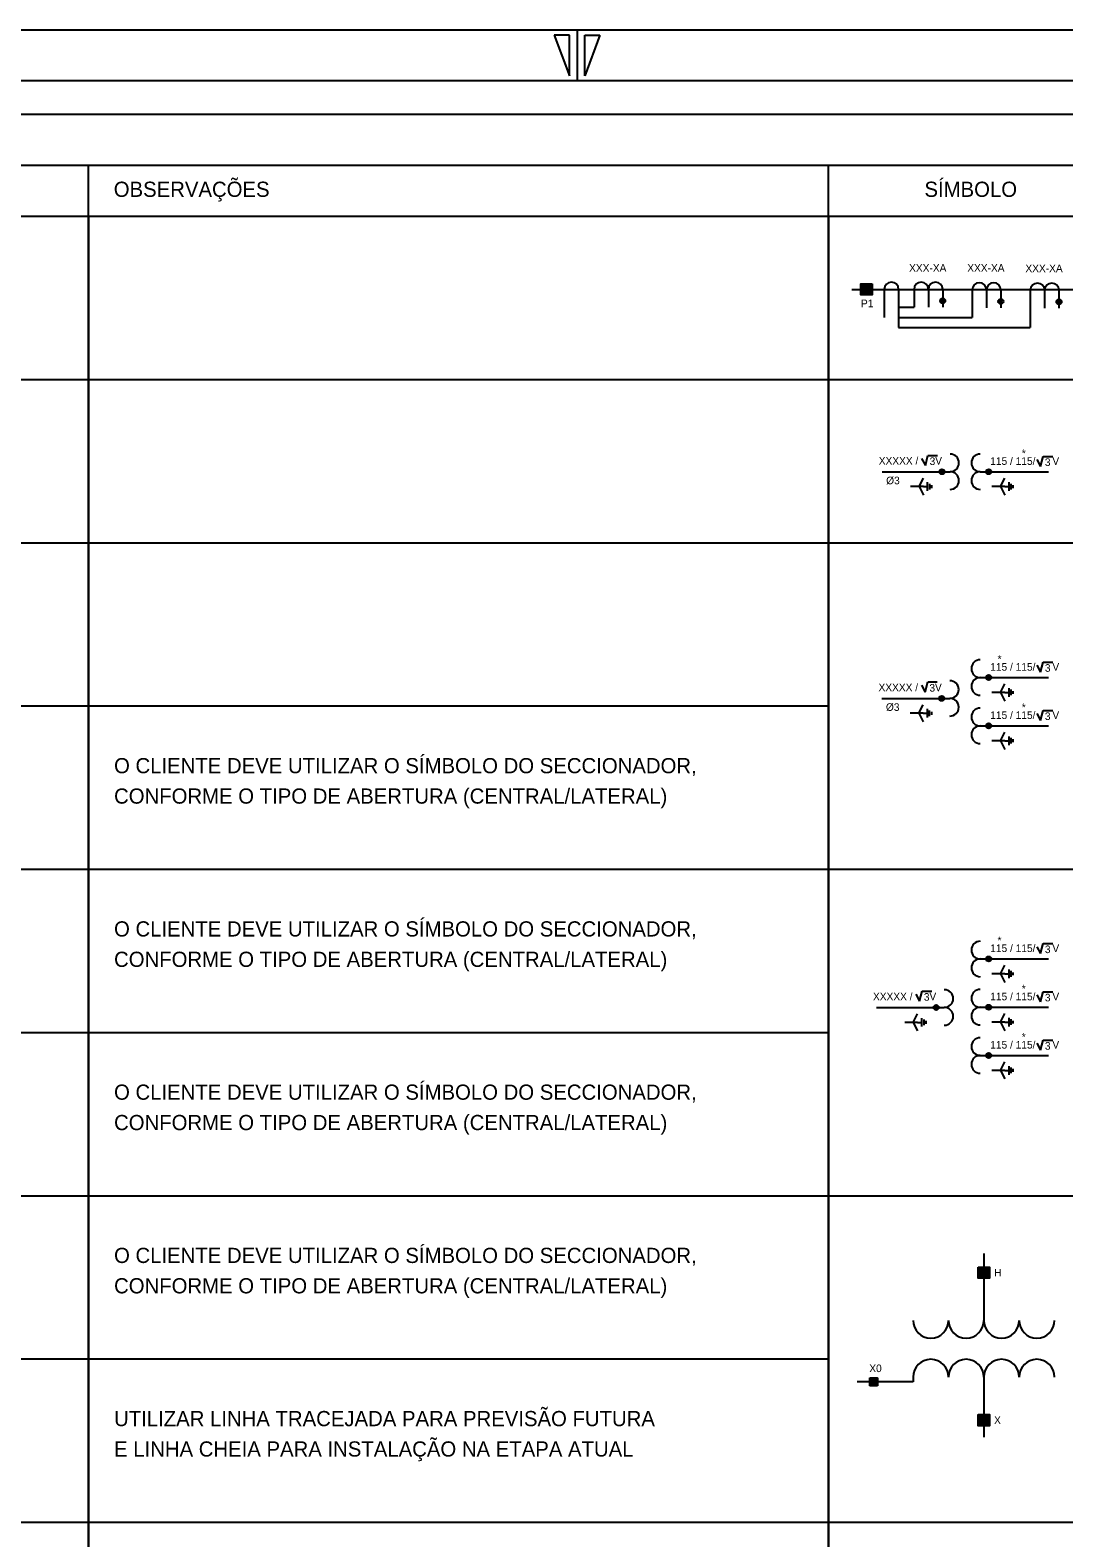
# Model space of a CAD drawing. Extents: x 563 to 3226, y 358 to 960.
# Drawn here: x 795.6 to 999.7, y 654.3 to 952 of the extents above; entities that cross this region are included whole.
import ezdxf

# ---------------------------------------------------------------- set-up
doc = ezdxf.new("R2010")
doc.units = 0
for name, color, linetype in [('COMENTÁRIOS_CEMIG_03-12-2019', 7, 'Continuous'), ('Default', 7, 'Continuous'), ('New Level (0)', 7, 'Continuous')]:
    doc.layers.add(name, color=color, linetype=linetype)

msp = doc.modelspace()

# ---------------------------------------------------------------- linework, layer by layer
at = {"layer": 'COMENTÁRIOS_CEMIG_03-12-2019'}
for p, q in [((959.63, 901.76), (961.72, 899.67)), ((959.63, 901.58), (961.54, 899.67)), ((959.63, 901.41), (961.37, 899.67)), ((959.63, 901.23), (961.19, 899.67)), ((959.63, 901.05), (961.01, 899.67)), ((959.63, 900.88), (960.84, 899.67)), ((959.63, 900.7), (960.66, 899.67)), ((959.63, 900.52), (960.48, 899.67)), ((959.63, 900.35), (960.31, 899.67)), ((959.63, 900.17), (960.13, 899.67)), ((959.63, 899.99), (959.95, 899.67)), ((959.63, 899.82), (959.78, 899.67)), ((959.69, 901.88), (961.84, 899.73)), ((959.86, 901.88), (961.84, 899.9)), ((960.04, 901.88), (961.84, 900.08)), ((960.22, 901.88), (961.84, 900.26)), ((960.39, 901.88), (961.84, 900.43)), ((960.57, 901.88), (961.84, 900.61)), ((960.75, 901.88), (961.84, 900.79)), ((960.92, 901.88), (961.84, 900.96)), ((961.1, 901.88), (961.84, 901.14)), ((961.28, 901.88), (961.84, 901.32)), ((961.45, 901.88), (961.84, 901.49)), ((961.63, 901.88), (961.84, 901.67)), ((961.81, 901.88), (961.84, 901.85)), ((982.78, 705.59), (984.93, 707.74)), ((982.78, 705.76), (984.75, 707.74)), ((982.78, 705.94), (984.57, 707.74)), ((982.78, 706.12), (984.4, 707.74)), ((982.78, 706.29), (984.22, 707.74)), ((982.78, 706.47), (984.04, 707.74)), ((982.78, 706.65), (983.87, 707.74)), ((982.78, 706.83), (983.69, 707.74)), ((982.78, 707), (983.51, 707.74)), ((982.78, 707.18), (983.34, 707.74)), ((982.78, 707.36), (983.16, 707.74)), ((982.78, 707.53), (982.98, 707.74)), ((982.78, 707.71), (982.81, 707.74)), ((982.89, 705.53), (984.99, 707.62)), ((983.07, 705.53), (984.99, 707.45)), ((983.25, 705.53), (984.99, 707.27)), ((983.42, 705.53), (984.99, 707.09)), ((983.6, 705.53), (984.99, 706.92)), ((983.78, 705.53), (984.99, 706.74)), ((983.95, 705.53), (984.99, 706.56)), ((984.13, 705.53), (984.99, 706.38)), ((984.31, 705.53), (984.99, 706.21)), ((984.49, 705.53), (984.99, 706.03)), ((984.66, 705.53), (984.99, 705.85)), ((984.84, 705.53), (984.99, 705.68)), ((982.78, 676.47), (984.93, 678.62)), ((982.78, 676.65), (984.75, 678.62)), ((982.78, 676.82), (984.57, 678.62)), ((982.78, 677), (984.4, 678.62)), ((982.78, 677.18), (984.22, 678.62)), ((982.78, 677.35), (984.04, 678.62)), ((982.78, 677.53), (983.87, 678.62)), ((982.78, 677.71), (983.69, 678.62)), ((982.78, 677.88), (983.51, 678.62)), ((982.78, 678.06), (983.34, 678.62)), ((982.78, 678.24), (983.16, 678.62)), ((982.78, 678.41), (982.98, 678.62)), ((982.78, 678.59), (982.81, 678.62)), ((982.89, 676.41), (984.99, 678.5)), ((983.07, 676.41), (984.99, 678.33)), ((983.25, 676.41), (984.99, 678.15)), ((983.42, 676.41), (984.99, 677.97)), ((983.6, 676.41), (984.99, 677.8)), ((983.78, 676.41), (984.99, 677.62)), ((983.95, 676.41), (984.99, 677.44)), ((984.13, 676.41), (984.99, 677.27)), ((984.31, 676.41), (984.99, 677.09)), ((984.49, 676.41), (984.99, 676.91)), ((984.66, 676.41), (984.99, 676.73)), ((984.84, 676.41), (984.99, 676.56))]:
    msp.add_line(p, q, dxfattribs=at)
for points in [[(961.84, 901.88), (961.84, 899.67), (959.63, 899.67), (959.63, 901.88)], [(982.78, 707.74), (984.99, 707.74), (984.99, 705.53), (982.78, 705.53)], [(982.78, 678.62), (984.99, 678.62), (984.99, 676.41), (982.78, 676.41)]]:
    msp.add_lwpolyline(points, close=True, dxfattribs=at)
at = {"layer": 'Default'}
for p, q in [((957.79, 900.78), (1006.04, 900.78)), ((964.22, 900.78), (964.22, 895.24)), ((964.22, 900.78), (964.22, 895.24)), ((967.05, 900.78), (967.05, 897.24)), ((967.05, 900.78), (967.05, 893.24)), ((970.1, 900.78), (970.1, 897.24)), ((970.1, 900.78), (970.1, 897.24)), ((972.93, 900.78), (972.93, 897.24)), ((972.93, 900.78), (972.93, 897.24)), ((975.76, 900.78), (975.76, 897.24)), ((975.76, 900.78), (975.76, 897.24)), ((981.58, 900.68), (981.58, 895.24)), ((984.41, 900.68), (984.41, 897.15)), ((987.24, 900.68), (987.24, 897.15)), ((993.06, 900.59), (993.06, 893.24)), ((995.89, 900.59), (995.89, 897.05)), ((998.72, 900.59), (998.72, 897.05)), ((967.05, 897.24), (970.1, 897.24)), ((967.05, 895.24), (981.58, 895.24)), ((967.05, 893.24), (993.06, 893.24)), ((971.6, 867.37), (972.35, 866)), ((972.35, 866), (972.85, 868)), ((972.85, 868), (974.74, 868)), ((994.35, 867.19), (995.1, 865.81)), ((995.1, 865.81), (995.6, 867.81)), ((995.6, 867.81), (997.49, 867.81)), ((963.81, 864.77), (977.22, 864.77)), ((971.09, 861.83), (971.94, 863.53)), ((983.17, 864.77), (996.68, 864.77)), ((987.15, 861.83), (988, 863.53)), ((971.09, 861.83), (969.4, 861.83)), ((971.94, 861.83), (971.09, 861.83)), ((971.09, 861.83), (971.94, 860.13)), ((971.94, 861.83), (972.79, 861.83)), ((972.79, 861.83), (972.79, 862.68)), ((972.79, 860.98), (972.79, 861.83)), ((973.22, 861.83), (973.22, 862.39)), ((973.22, 861.26), (973.22, 861.83)), ((973.64, 861.83), (973.64, 862.11)), ((973.64, 861.54), (973.64, 861.83)), ((987.15, 861.83), (985.46, 861.83)), ((988, 861.83), (987.15, 861.83)), ((987.15, 861.83), (988, 860.13)), ((988, 861.83), (988.85, 861.83)), ((988.85, 861.83), (988.85, 862.68)), ((988.85, 860.98), (988.85, 861.83)), ((989.28, 861.83), (989.28, 862.39)), ((989.28, 861.26), (989.28, 861.83)), ((989.7, 861.83), (989.7, 862.11)), ((989.7, 861.54), (989.7, 861.83)), ((994.35, 826.55), (995.1, 825.18)), ((995.1, 825.18), (995.6, 827.18)), ((995.6, 827.18), (997.49, 827.18)), ((971.55, 822.63), (972.31, 821.25)), ((972.31, 821.25), (972.81, 823.26)), ((972.81, 823.26), (974.69, 823.26)), ((983.17, 824.14), (996.68, 824.14)), ((987.15, 821.2), (988, 822.89)), ((988.85, 821.2), (988.85, 822.04)), ((989.28, 821.2), (989.28, 821.76)), ((963.76, 820.02), (977.17, 820.02)), ((971.05, 817.08), (971.9, 818.78)), ((987.15, 821.2), (985.46, 821.2)), ((988, 821.2), (987.15, 821.2)), ((987.15, 821.2), (988, 819.5)), ((988, 821.2), (988.85, 821.2)), ((988.85, 820.35), (988.85, 821.2)), ((989.28, 820.63), (989.28, 821.2)), ((989.7, 821.2), (989.7, 821.48)), ((989.7, 820.91), (989.7, 821.2)), ((971.05, 817.08), (969.35, 817.08)), ((971.9, 817.08), (971.05, 817.08)), ((971.05, 817.08), (971.9, 815.39)), ((971.9, 817.08), (972.75, 817.08)), ((972.75, 817.08), (972.75, 817.93)), ((972.75, 816.24), (972.75, 817.08)), ((973.17, 817.08), (973.17, 817.64)), ((973.17, 816.52), (973.17, 817.08)), ((973.6, 817.08), (973.6, 817.36)), ((973.6, 816.8), (973.6, 817.08)), ((994.35, 817.02), (995.1, 815.65)), ((995.1, 815.65), (995.6, 817.65)), ((995.6, 817.65), (997.49, 817.65)), ((996.68, 814.55), (982.77, 814.55)), ((987.15, 811.66), (988, 813.36)), ((987.15, 811.66), (985.46, 811.66)), ((988, 811.66), (987.15, 811.66)), ((987.15, 811.66), (988, 809.96)), ((988, 811.66), (988.85, 811.66)), ((988.85, 811.66), (988.85, 812.51)), ((988.85, 810.81), (988.85, 811.66)), ((989.28, 811.66), (989.28, 812.22)), ((989.28, 811.09), (989.28, 811.66)), ((989.7, 811.66), (989.7, 811.94)), ((989.7, 811.37), (989.7, 811.66)), ((994.35, 771), (995.1, 769.63)), ((995.1, 769.63), (995.6, 771.63)), ((995.6, 771.63), (997.49, 771.63)), ((983.17, 768.58), (996.68, 768.58)), ((987.15, 765.64), (985.46, 765.64)), ((987.15, 765.64), (988, 767.34)), ((988, 765.64), (987.15, 765.64)), ((987.15, 765.64), (988, 763.95)), ((988, 765.64), (988.85, 765.64)), ((988.85, 765.64), (988.85, 766.49)), ((988.85, 764.8), (988.85, 765.64)), ((989.28, 765.64), (989.28, 766.2)), ((989.28, 765.08), (989.28, 765.64)), ((989.7, 765.64), (989.7, 765.92)), ((989.7, 765.36), (989.7, 765.64)), ((971.21, 760.23), (971.71, 762.23)), ((971.71, 762.23), (973.6, 762.23)), ((995.1, 760.09), (995.6, 762.1)), ((995.6, 762.1), (997.49, 762.1)), ((970.46, 761.61), (971.21, 760.23)), ((994.35, 761.47), (995.1, 760.09)), ((962.67, 759), (976.08, 759)), ((969.96, 756.06), (970.81, 757.76)), ((971.65, 756.06), (971.65, 756.91)), ((972.08, 756.06), (972.08, 756.62)), ((972.5, 756.06), (972.5, 756.34)), ((996.68, 759), (982.77, 759)), ((987.15, 756.11), (985.46, 756.11)), ((987.15, 756.11), (988, 757.81)), ((988, 756.11), (987.15, 756.11)), ((987.15, 756.11), (988, 754.41)), ((988, 756.11), (988.85, 756.11)), ((988.85, 756.11), (988.85, 756.96)), ((988.85, 755.26), (988.85, 756.11)), ((989.28, 756.11), (989.28, 756.67)), ((989.28, 755.54), (989.28, 756.11)), ((989.7, 756.11), (989.7, 756.39)), ((989.7, 755.82), (989.7, 756.11)), ((969.96, 756.06), (968.26, 756.06)), ((970.81, 756.06), (969.96, 756.06)), ((969.96, 756.06), (970.81, 754.36)), ((970.81, 756.06), (971.65, 756.06)), ((971.65, 755.21), (971.65, 756.06)), ((972.08, 755.49), (972.08, 756.06)), ((972.5, 755.77), (972.5, 756.06)), ((994.35, 751.94), (995.1, 750.56)), ((995.1, 750.56), (995.6, 752.56)), ((995.6, 752.56), (997.49, 752.56)), ((996.68, 749.47), (982.77, 749.47)), ((987.15, 746.58), (988, 748.28)), ((988.85, 746.58), (988.85, 747.43)), ((987.15, 746.58), (985.46, 746.58)), ((988, 746.58), (987.15, 746.58)), ((987.15, 746.58), (988, 744.88)), ((988, 746.58), (988.85, 746.58)), ((988.85, 745.73), (988.85, 746.58)), ((989.28, 746.58), (989.28, 747.14)), ((989.28, 746.01), (989.28, 746.58)), ((989.7, 746.58), (989.7, 746.86)), ((989.7, 746.29), (989.7, 746.58)), ((983.88, 710.42), (983.88, 697.19)), ((969.92, 685.07), (958.87, 685.07)), ((961.35, 685.85), (962.91, 685.85)), ((961.35, 684.3), (961.35, 685.85)), ((962.79, 684.3), (961.35, 685.73)), ((962.65, 684.3), (961.35, 685.6)), ((962.51, 684.3), (961.35, 685.46)), ((962.38, 684.3), (961.35, 685.32)), ((962.24, 684.3), (961.35, 685.18)), ((962.1, 684.3), (961.35, 685.05)), ((961.96, 684.3), (961.35, 684.91)), ((961.82, 684.3), (961.35, 684.77)), ((962.91, 684.32), (961.37, 685.85)), ((962.91, 684.45), (961.51, 685.85)), ((962.91, 684.59), (961.64, 685.85)), ((962.91, 684.73), (961.78, 685.85)), ((962.91, 684.87), (961.92, 685.85)), ((962.91, 685), (962.06, 685.85)), ((962.91, 685.14), (962.19, 685.85)), ((962.91, 685.28), (962.33, 685.85)), ((962.91, 685.42), (962.47, 685.85)), ((962.91, 685.55), (962.61, 685.85)), ((962.91, 685.69), (962.74, 685.85)), ((962.91, 685.83), (962.88, 685.85)), ((962.91, 685.85), (962.91, 684.3)), ((969.92, 686.04), (969.92, 685.07)), ((983.88, 686.04), (983.88, 674.17)), ((961.69, 684.3), (961.35, 684.63)), ((961.55, 684.3), (961.35, 684.5)), ((961.41, 684.3), (961.35, 684.36)), ((962.91, 684.3), (961.35, 684.3))]:
    msp.add_line(p, q, dxfattribs=at)
for centre, radius in [((975.76, 898.51), 0.501), ((975.76, 898.51), 0.282), ((987.24, 898.41), 0.501), ((987.24, 898.41), 0.282), ((998.72, 898.32), 0.501), ((998.72, 898.32), 0.282), ((975.61, 864.77), 0.501), ((975.61, 864.77), 0.282), ((984.85, 864.77), 0.501), ((984.85, 864.77), 0.282), ((984.85, 824.14), 0.501), ((984.85, 824.14), 0.282), ((975.56, 820.02), 0.501), ((975.56, 820.02), 0.282), ((984.85, 814.6), 0.501), ((984.85, 814.6), 0.282), ((984.85, 768.58), 0.501), ((984.85, 768.58), 0.282), ((974.47, 759), 0.501), ((974.47, 759), 0.282), ((984.85, 759.05), 0.501), ((984.85, 759.05), 0.282), ((984.85, 749.52), 0.501), ((984.85, 749.52), 0.282)]:
    msp.add_circle(centre, radius, dxfattribs=at)
for centre, radius, start, end in [((965.64, 900.78), 1.42, 0, 180), ((965.64, 900.78), 1.42, 0, 180), ((971.52, 900.78), 1.42, 0, 180), ((971.52, 900.78), 1.42, 0, 180), ((974.35, 900.78), 1.42, 0, 180), ((974.35, 900.78), 1.42, 0, 180), ((983, 900.68), 1.42, 0, 180), ((985.83, 900.68), 1.42, 0, 180), ((994.48, 900.59), 1.42, 0, 180), ((997.31, 900.59), 1.42, 0, 180), ((977.22, 866.52), 1.75, 270, 90), ((983.17, 866.52), 1.75, 90, 270), ((977.22, 863.02), 1.75, 270, 90), ((983.17, 863.02), 1.75, 90, 270), ((983.17, 825.89), 1.75, 90, 270), ((977.17, 821.77), 1.75, 270, 90), ((983.17, 822.39), 1.75, 90, 270), ((977.17, 818.27), 1.75, 270, 90), ((983.17, 816.35), 1.75, 90, 270), ((983.17, 812.85), 1.75, 90, 270), ((983.17, 770.33), 1.75, 90, 270), ((983.17, 766.83), 1.75, 90, 270), ((976.08, 760.75), 1.75, 270, 90), ((983.17, 760.8), 1.75, 90, 270), ((976.08, 757.25), 1.75, 270, 90), ((983.17, 757.3), 1.75, 90, 270), ((983.17, 751.27), 1.75, 90, 270), ((983.17, 747.77), 1.75, 90, 270), ((973.41, 697.21), 3.49, 180, 0), ((980.39, 697.21), 3.49, 180, 0), ((987.37, 697.21), 3.49, 180, 0), ((994.35, 697.21), 3.49, 180, 0), ((973.41, 686.04), 3.49, 0, 180), ((980.39, 686.04), 3.49, 0, 180), ((987.37, 686.04), 3.49, 0, 180), ((994.35, 686.04), 3.49, 0, 180)]:
    msp.add_arc(centre, radius, start, end, dxfattribs=at)
at = {"layer": 'New Level (0)'}
for p, q in [((1403.58, 951.96), (562.58, 951.96)), ((1403.58, 951.96), (562.58, 951.96)), ((902.08, 950.96), (899.08, 950.96)), ((899.08, 950.96), (902.08, 942.96)), ((902.08, 942.96), (902.08, 950.96)), ((903.58, 951.96), (903.58, 941.96)), ((905.08, 942.96), (905.08, 950.96)), ((905.08, 950.96), (908.08, 950.96)), ((908.08, 950.96), (905.08, 942.96)), ((1393.58, 941.96), (572.58, 941.96)), ((603.14, 935.35), (1303.31, 935.35)), ((603.14, 925.28), (974.81, 925.28)), ((807.1, 915.21), (807.1, 925.28)), ((953.22, 915.21), (953.22, 925.28)), ((953.22, 923.47), (953.22, 925.28)), ((953.22, 925.28), (1303.31, 925.28)), ((953.22, 915.21), (953.22, 923.47)), ((603.14, 882.98), (1303.31, 882.98)), ((603.14, 850.75), (1303.31, 850.75)), ((603.14, 818.53), (953.22, 818.53)), ((603.14, 786.3), (1303.31, 786.3)), ((603.14, 754.07), (953.22, 754.07)), ((603.14, 721.84), (1303.31, 721.84)), ((603.14, 689.61), (953.22, 689.61)), ((603.14, 657.39), (1303.31, 657.39))]:
    msp.add_line(p, q, dxfattribs=at)
for points in [[(603.14, 915.21), (807.1, 915.21), (807.1, 429.83), (603.14, 429.83)], [(807.1, 915.21), (953.22, 915.21), (953.22, 429.83), (807.1, 429.83)], [(953.22, 915.21), (1157.18, 915.21), (1157.18, 429.83), (953.22, 429.83)]]:
    msp.add_lwpolyline(points, close=True, dxfattribs=at)

# ---------------------------------------------------------------- texts
at = {"layer": 'Default'}
for s, height, p in [('OBSERVAÇÕES', 3, (812.11, 919.04)), ('SÍMBOLO', 3, (972.16, 919.04)), ('XXX-XA', 1.5, (969.13, 904.26)), ('XXX-XA', 1.5, (980.61, 904.26)), ('XXX-XA', 1.5, (992.09, 904.17)), ('P1', 1.5, (959.63, 897.25)), ('XXXXX /      V', 1.5, (963.14, 866.18)), ('3', 1.5, (973.18, 866.1)), ('115 / 115/      V', 1.5, (985.15, 866.13)), ('*', 1.5, (991.38, 867.68)), ('3', 1.5, (995.93, 865.91)), ('Ø3', 1.5, (964.6, 862.3)), ('*', 1.5, (986.59, 827.05)), ('115 / 115/      V', 1.5, (985.15, 825.49)), ('3', 1.5, (995.93, 825.28)), ('XXXXX /      V', 1.5, (963.09, 821.44)), ('3', 1.5, (973.14, 821.36)), ('Ø3', 1.5, (964.55, 817.56)), ('*', 1.5, (991.38, 817.52)), ('115 / 115/      V', 1.5, (985.15, 815.96)), ('3', 1.5, (995.93, 815.75)), ('O CLIENTE DEVE UTILIZAR O SÍMBOLO DO SECCIONADOR, ', 3, (812.17, 805.24)), ('CONFORME O TIPO DE ABERTURA (CENTRAL/LATERAL)', 3, (812.17, 799.24)), ('O CLIENTE DEVE UTILIZAR O SÍMBOLO DO SECCIONADOR, ', 3, (812.17, 773.01)), ('115 / 115/      V', 1.5, (985.15, 769.94)), ('*', 1.5, (986.59, 771.5)), ('3', 1.5, (995.93, 769.73)), ('CONFORME O TIPO DE ABERTURA (CENTRAL/LATERAL)', 3, (812.17, 767.01)), ('*', 1.5, (991.38, 761.97)), ('XXXXX /      V', 1.5, (962, 760.42)), ('3', 1.5, (972.04, 760.33)), ('115 / 115/      V', 1.5, (985.15, 760.41)), ('3', 1.5, (995.93, 760.2)), ('*', 1.5, (991.38, 752.43)), ('115 / 115/      V', 1.5, (985.15, 750.88)), ('3', 1.5, (995.93, 750.66)), ('O CLIENTE DEVE UTILIZAR O SÍMBOLO DO SECCIONADOR, ', 3, (812.17, 740.78)), ('CONFORME O TIPO DE ABERTURA (CENTRAL/LATERAL)', 3, (812.17, 734.78)), ('O CLIENTE DEVE UTILIZAR O SÍMBOLO DO SECCIONADOR, ', 3, (812.17, 708.55)), ('CONFORME O TIPO DE ABERTURA (CENTRAL/LATERAL)', 3, (812.17, 702.55)), ('H', 1.5, (985.91, 705.89)), ('X0', 1.5, (961.27, 687.01)), ('UTILIZAR LINHA TRACEJADA PARA PREVISÃO FUTURA', 3, (812.17, 676.33)), ('X', 1.5, (985.91, 676.77)), ('E LINHA CHEIA PARA INSTALAÇÃO NA ETAPA ATUAL', 3, (812.17, 670.33))]:
    msp.add_text(s, height=height, dxfattribs=at).set_placement(p)

doc.saveas('drawing.dxf')
